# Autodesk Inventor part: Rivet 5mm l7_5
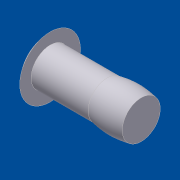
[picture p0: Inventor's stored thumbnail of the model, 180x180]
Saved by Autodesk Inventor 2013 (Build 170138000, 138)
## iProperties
Shininess: 50.0
Length Units: 11269
Angle Units: 11279
Time Units: 11290
Mass Units: 11283
Length Display Precision: 3
Angle Display Precision: 2
Created: 2001-04
Part Number: Rivet 5mm l7_5
Material: Standard
Document SubType Name: Modellieren
Designer: dl
Density: 1 g/cm^3
Density: 0.0
Volumn: 0.0
Area: 0.0
PropertySet Name: Model Information
Control State: 0
Master: False
Checked Out: False
Author: dl
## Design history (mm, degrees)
body "Solid1"
sketch "Sketch2"
  geometry: C1 r 1.5 at (0, 0) reference; 1 further point
  constraints: 1 coincident
revolve "Revolution1" stored, may be unused: angle "d8" = 90 deg
hole "Hole1" sketch "Sketch2" diameter "d10" = 2; stored, may be unused: countersink angle "d14" = 60 deg, drill point angle "d16" = 118 deg; dims "d11" = 6, "d12" = 4, "d13" = 2, "d15" = 5
sketch "Sketch1"
  geometry: L1 (0, 4.762)-(0, 6.262); L2 (1.5, 8.762)-(1.5, 7.262); L3 (1.5, 7.262)-(9, 7.262); L4 (13.5, 7.262)-(13.5, 4.762); L5 (13.5, 4.762)-(0, 4.762); A1 r 7.508 centre (7.066, 3.722) between (1.5, 8.762) and (0, 6.262); A2 r 10 centre (11.25, -2.482) between (13.5, 7.262) and (9, 7.262)
  constraints: 10 end point, 4 point on circle, 2 centre point, 2 parallel, 1 horizontal, 1 perpendicular, 1 vertical
  dimensions: "d0" = 1.5 distance of L1.start L1.end; "d1" = 4 vertical distance of L1.start L2.start; "d2" = 2.5 distance from line of L4.end L3; "d3" = 1.5 distance between parallel lines of L2 L1; "d4" = 7.5 distance of L2.end L3.end; "d5" = 10 radius of A2; "d6" = 13.5 distance of L4.end L1.start; "d7" = 2.25 horizontal distance of L3.end A2.centre
